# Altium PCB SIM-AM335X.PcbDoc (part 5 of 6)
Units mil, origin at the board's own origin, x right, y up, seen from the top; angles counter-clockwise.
Board outline 4041.51 x 2715.24 mil, 2 copper layers (Top Layer, Bottom Layer); 172 components, 190 nets, 855 pads, 317 vias.
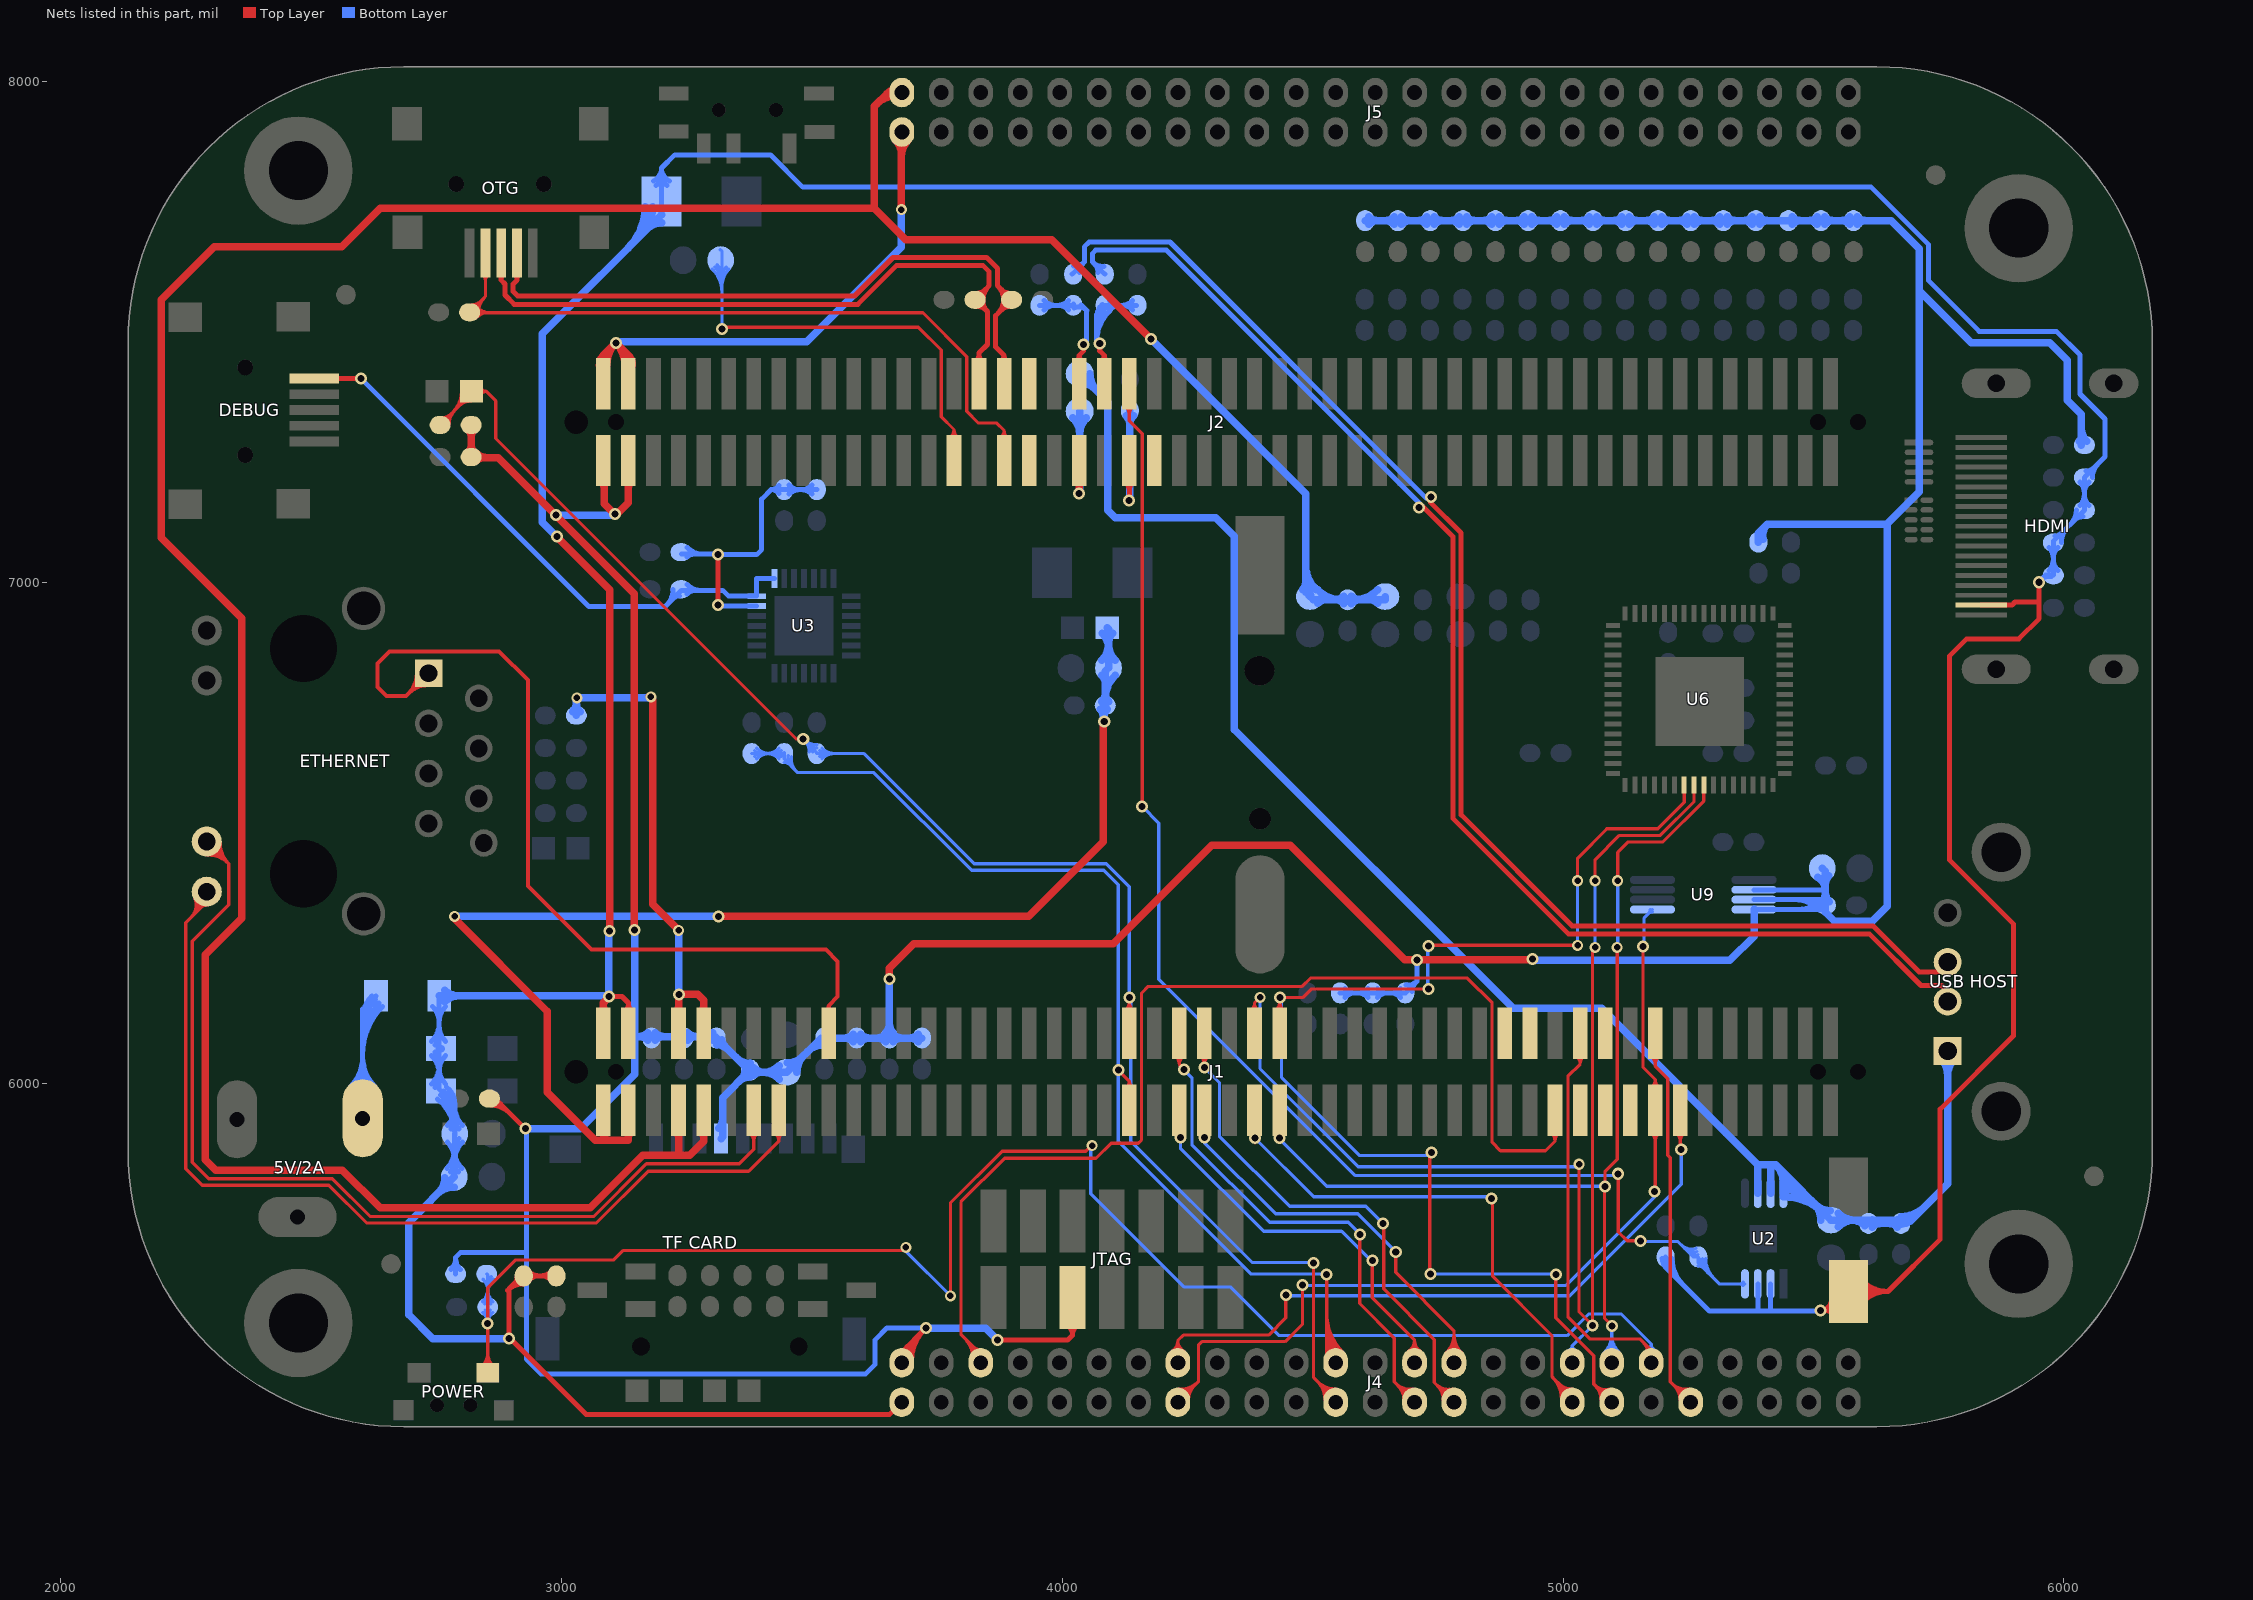
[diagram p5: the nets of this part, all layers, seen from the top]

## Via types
v1: diameter 24, hole 14, Top Layer to Bottom Layer, tented both sides, 206 vias
v2: diameter 22, hole 13, Top Layer to Bottom Layer, tented both sides, 109 vias
v3: diameter 22, hole 14, Top Layer to Bottom Layer, tented both sides, 2 vias

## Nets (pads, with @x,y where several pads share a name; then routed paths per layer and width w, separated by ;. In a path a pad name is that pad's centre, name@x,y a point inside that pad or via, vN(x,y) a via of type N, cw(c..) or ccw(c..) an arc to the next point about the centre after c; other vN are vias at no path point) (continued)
PHY_TX_P: ETHERNET.1 J1.20 | length 1923.7
  Top Layer w8: ETHERNET.1@2711.5,6819.2 cw(c2654.77,6819.2) 2694.88,6779.08 cw(c2735,6738.97) ETHERNET.1@2735,6795.7 ; ETHERNET.1@2719.5,6819.2 cw(c2682.08,6819.2) 2708.54,6792.74 cw(c2735,6766.28) ETHERNET.1@2735,6803.7 ; ETHERNET.1@2735,6819.2 2689.8,6774 2651,6774 2633,6792 2633,6839 2657,6863 2876,6863 2933,6806 2933,6394.49 3059.99,6267.5 3528.5,6267.5 3551.75,6244.25 3551.75,6173.75 3534,6156 ; J1.20@3528.49,6146.17 ccw(c3522.49,6156) 3534,6156 ; J1.20@3534,6100.54 3534,6156 ; J1.20@3539.51,6146.17 cw(c3545.51,6156) 3534,6156
PMIC_INT: J1.81
PMIC_POWR_EN: J1.74
PMIC_RESETOUT: J1.82 | length 5.3
  Top Layer w6.5: J1.82@5084,6100.54 J1.82@5087.75,6096.79
PORZN: J1.83
POWR_EN: J1.76
PWR_BUT: J1.80 J4.40 POWER.1 R41.1 R43.1 | length 4479.4
  Top Layer w6.5: POWER.1@2841.38,5434.12 ccw(c2813.32,5462.18) 2853,5462.18 ccw(c2892.68,5462.18) POWER.1@2864.62,5434.12 ; POWER.1@2845.97,5429.53 ccw(c2829.01,5446.49) 2853,5446.49 ccw(c2876.99,5446.49) POWER.1@2860.03,5429.53 ; POWER.1@2853,5422.5 v1(2853,5521) 2853,5592 2909,5648 3105,5648 3124,5667 3682,5667 v2(3688,5673) ; v2@3691,5670 v2@3694,5673 ; v2(3777,5576) 3777,5762 3880,5865 4047,5865 v2@4062,5880 ; J1.80@5026.55,6055.41 cw(c5012.2,6039) 5034,6039 ; J1.80@5034,6100.54 5034,6039 ; J1.80@5041.45,6055.41 ccw(c5055.8,6039) 5034,6039 ; 5159.18,5484.82 cw(c5134.48,5460.12) J4.40@5167.93,5450.07 ; 5166.87,5477.13 cw(c5146.3,5456.57) J4.40@5174.15,5448.2 ; J4.40@5175.93,5442.74 5175.93,5468.07 5154,5490 5054,5490 5009.68,5534.32 5009.68,6014.68 5034,6039
  Bottom Layer w6.5: R43.1@2842.57,5564.43 ccw(c2817.39,5589.61) 2853,5589.61 ccw(c2888.61,5589.61) R43.1@2863.43,5564.43 ; R43.1@2843.16,5543.01 cw(c2823.46,5521) v1(2853,5521) ; R41.1@2843.57,5609.57 cw(c2820.8,5586.8) 2853,5586.8 ; R43.1@2847.17,5559.83 ccw(c2833.08,5573.92) 2853,5573.92 ccw(c2872.92,5573.92) R43.1@2858.83,5559.83 ; R43.1@2847.5,5547.85 cw(c2836.48,5535.54) 2853,5535.54 cw(c2869.52,5535.54) R43.1@2858.5,5547.85 ; R41.1@2851,5620 2853,5618 R43.1@2853,5554 v1(2853,5521) ; 2853,5581.98 cw(c2892.02,5581.98) R41.1@2864.43,5609.57 ; 2853,5597.67 cw(c2876.33,5597.67) R41.1@2859.83,5614.17 ; R43.1@2862.84,5543.01 ccw(c2882.54,5521) v1(2853,5521) ; v2(3688,5673) 3688,5665 v2(3777,5576) ; v2@4061,5873 4057,5869 4057,5780 4243,5594 4336,5594 4433,5497 5008,5497 5051,5540 5116,5540 5175.93,5480.07 ; J4.40@5167.51,5467.29 ccw(c5162.02,5480.07) 5175.93,5480.07 ; J4.40@5175.93,5442.74 5175.93,5480.07 ; J4.40@5184.35,5467.29 cw(c5189.84,5480.07) 5175.93,5480.07
  other v2: 4060,5876
RTC_PORZN: J1.79
SPI1_CS0: J1.55 J4.38 U6.25 | length 2131.6
  Top Layer w6.5: v1@5083,5795 5083,5531 v1(5098,5516) ; v1(5084,5795) 5084,5824.76 5108.32,5849.08 5108.32,6264.68 5102,6271 5103,6272 v2(5108,6272) ; v2(5109,6405) 5109,6461.5 5130,6482.5 5199.62,6482.5 5281.16,6564.04 U6.25@5281.16,6595.99
  Bottom Layer w6.5: v1@4434,5889 4528,5795 v1(5084,5795) ; J4.38@5082.09,5462.76 ccw(c5045.63,5499.22) 5097.19,5499.22 ccw(c5148.75,5499.22) J4.38@5112.29,5462.76 ; J4.38@5086.69,5458.17 ccw(c5061.32,5483.53) 5097.19,5483.53 ccw(c5133.06,5483.53) J4.38@5107.69,5458.17 ; J4.38@5097.19,5442.74 v1@5097.19,5512.19 ; v2(5108,6272) 5103,6272 5109,6266 v2(5109,6405)
  other v1: 4434,5891
SPI1_D0: J1.54 J4.36 U6.24 | length 2634.2
  Top Layer w6.5: J1.54@4376.85,6145.93 ccw(c4364.55,6161) 4384,6161 ; J1.54@4384,6100.54 4384,6161 ; J1.54@4391.15,6145.93 cw(c4403.45,6161) 4384,6161 ; v2(4395,6172) 4384,6161 ; v2@5032,5842 v2(5032,5839) 5032,5544 v1(5059,5517) 5059,6267 v2(5064,6272) ; v2(5064,6405) 5064,6447 5112.5,6495.5 5194.24,6495.5 5261.47,6562.73 U6.24@5261.47,6595.99
  Bottom Layer w6.5: v2(4395,6172) 4395,6030 4591,5834 5024,5834 v2@5032,5842 ; J4.36@5012.26,5468.1 ccw(c5009.73,5476.45) 5018.45,5476.45 ; J4.36@5018.45,5442.74 5018.45,5476.45 ; J4.36@5024.64,5468.1 cw(c5027.17,5476.45) 5018.45,5476.45 ; v1(5059,5517) 5018.45,5476.45 ; v2(5064,6272) v2(5064,6405)
SPI1_D1: J1.53 J4.35 | length 1263.7
  Top Layer w6.5: J1.53@4376,5902.38 cw(c4356.68,5883.06) 4384,5883.06 cw(c4411.32,5883.06) J1.53@4392,5902.38 ; J1.53@4384,5947 4384,5883 v1@4385,5882 ; v1@4859,5769 4859,5616 4978,5497 4978,5415 ; 4989.11,5403.89 cw(c4954.14,5368.92) J4.35@5003.59,5368.92 ; 4991.6,5401.4 ccw(c5018.45,5428.25) J4.35@5018.45,5390.28 ; J4.35@4997.09,5368.92 ccw(c4931.95,5368.92) 4978.01,5414.99 ; 5000.2,5392.8 cw(c4976.33,5368.92) J4.35@5010.09,5368.92 ; 5002.7,5390.3 ccw(c5018.45,5406.05) J4.35@5018.45,5383.78 ; J4.35@5018.45,5364 5018.45,5374.55 4978,5415
  Bottom Layer w6.5: v1(4385,5891) 4502,5774 v1@4857,5774
  other v1: 4857,5771
SPI1_SCLK: J1.56 J4.37 U6.23 | length 2690.5
  Top Layer w6.5: J1.56@4426,6145.16 ccw(c4404.26,6166.89) v1@4435,6166.89 ; J1.56@4434,6100.54 4435,6101.54 v1(4435,6172) 4481,6172 4498,6189 v1(4731,6189) v1@4730,6188 ; v1@4435,6162.07 ccw(c4458.91,6162.07) J1.56@4442,6145.16 ; v1@4734,5619.77 4734,5857 v1@4737,5857 ; v1@4741,6275 4742,6276 v2(5029,6276) ; v1@4987,5619 v1@4987,5619.98 ; v2(5029,6405) 5029,6450 5087.75,6508.75
  Top Layer w7: v1@4987,5619 4985.8,5617.8 4985.8,5532.2 5061,5457 5061,5400.19 J4.37@5097.19,5364 ; 5063.46,5397.73 ccw(c5085.35,5419.61) J4.37@5092.39,5389.47 ; 5064.64,5396.55 cw(c5037.01,5368.92) J4.37@5076.08,5368.92 ; 5072.36,5388.83 ccw(c5088.72,5405.18) J4.37@5093.98,5382.66 ; 5076.59,5384.6 cw(c5060.91,5368.92) J4.37@5083.08,5368.92 ; 5087.75,6508.75 5188.75,6508.75 5241.78,6561.78 U6.23@5241.78,6595.99
  Bottom Layer w6.5: v1@4438,6170 4438,6012 4593.75,5856.25 v1@4734,5856.25 ; v1@4730,6188 4730,6280 4731,6279 v1(4731,6275) ; v1@4736.63,5619.98 v1@4987.43,5619.98 ; v2@5029,6273 v2(5029,6276) v2(5029,6405)
  other v1: 4986,5619 4735,5620 4737,5862
SYS_RESETN: J1.77 J4.6 | length 2428.2
  Top Layer w6.5: 3803.5,5493.5 cw(c3757.67,5447.66) J4.6@3822.49,5447.66 ; 3814.6,5482.4 cw(c3779.86,5447.66) J4.6@3828.99,5447.66 ; 3821.36,5475.64 ccw(c3837.35,5491.62) J4.6@3837.35,5469.02 ; 3825.7,5471.3 cw(c3802.05,5447.66) J4.6@3835.49,5447.66 ; J4.6@3837.35,5442.74 3837.35,5459.65 3797.75,5499.25 3797.75,5763.75 3885,5851 4067.54,5851 4097.54,5881 4152,5881 4158.32,5887.32 4158.32,6180.32 4172,6194 4479,6194 4495.75,6210.75 4809.04,6210.75 4858.32,6161.47 4858.32,5882.68 4875,5866 4965,5866 4984,5885 ; J1.77@4976.44,5901.97 cw(c4961.19,5885) 4984,5885 ; J1.77@4984,5947 4984,5885 ; J1.77@4991.56,5901.97 ccw(c5006.81,5885) 4984,5885
UART0_RX: J1.43 J4.24 R53.2 R54.1 | length 2750
  Top Layer w6.5: v1(4112,6027) 4134,6005 ; J1.43@4127.64,5992.97 ccw(c4119.45,6005) 4134,6005 ; J1.43@4134,5947 4134,6005 ; J1.43@4140.36,5992.97 cw(c4148.55,6005) 4134,6005 ; 4528,5479.93 ccw(c4578.27,5479.93) J4.24@4542.72,5444.38 ; 4528,5495.62 ccw(c4593.96,5495.62) J4.24@4547.32,5448.97 ; 4528,5511.31 ccw(c4609.66,5511.31) J4.24@4551.92,5453.57 ; 4528,5527 ccw(c4625.35,5527) J4.24@4556.51,5458.17 ; 4528,5542.69 ccw(c4641.04,5542.69) J4.24@4561.11,5462.76 ; v1(4528,5619) 4528,5460.75 J4.24@4546.01,5442.74
  Bottom Layer w6.5: R54.1@3380,6659 R53.2@3445,6659 ; R54.1@3385.83,6653.17 cw(c3399.92,6639.08) 3399.92,6659 cw(c3399.92,6678.92) R54.1@3385.83,6664.83 ; R54.1@3390.43,6648.57 cw(c3415.61,6623.39) 3415.61,6659 cw(c3415.61,6694.61) R54.1@3390.43,6669.43 ; R53.2@3434.57,6648.57 ccw(c3409.39,6623.39) 3409.39,6659 ccw(c3409.39,6694.61) R53.2@3434.57,6669.43 ; R53.2@3439.17,6653.17 ccw(c3425.08,6639.08) 3425.08,6659 ccw(c3425.08,6678.92) R53.2@3439.17,6664.83 ; R53.2@3445,6641.25 cw(c3445,6624.37) 3456.93,6636.31 ; R53.2@3445,6660.76 R53.2@3445,6659 ; R53.2@3453.11,6654.51 ccw(c3476.23,6650.25) 3459.61,6633.63 ; R53.2@3459.51,6653.33 ccw(c3491.01,6647.53) 3468.36,6624.88 ; v1(4528,5619) 4527.25,5619.75 4377.25,5619.75 4112,5885 v1(4112,6027) 4112,6397 4083,6426 3819,6426 3624,6621 3472.24,6621 3445,6648.24 R53.2@3445,6659
UART0_TX: J1.44 J4.23 LED3.2 R19.2 R52.2 | length 3800
  Top Layer w6.5: R19.2@2758,7315 2820.51,7377.51 LED3.2@2820.51,7382.2 2849.8,7382.2 ; R19.2@2761,7329.75 ccw(c2761,7358.12) 2781.06,7338.06 ; R19.2@2769.25,7315 cw(c2796.41,7315) 2777.2,7334.2 ; R19.2@2775.75,7315 cw(c2818.6,7315) 2788.3,7345.3 ; 2783.48,7340.48 ccw(c2741.77,7382.2) LED3.2@2800.76,7382.2 ; 2794.58,7351.58 ccw(c2763.97,7382.2) LED3.2@2807.26,7382.2 ; 2796,7353 cw(c2820.01,7328.99) LED3.2@2820.01,7362.95 ; LED3.2@2805.68,7362.68 ccw(c2786.16,7382.2) LED3.2@2813.76,7382.2 ; LED3.2@2838.8,7374.84 cw(c2849.8,7370.29) 2849.8,7382.2 ; LED3.2@2838.8,7389.55 ccw(c2849.8,7394.1) 2849.8,7382.2 ; v1(3483,6688) 3469,6688 2869,7288 2869,7363 2849.8,7382.2 ; J1.44@4126,6145.16 ccw(c4106.68,6164.48) 4134,6164.48 ccw(c4161.32,6164.48) J1.44@4142,6145.16 ; J1.44@4131,6097.54 J1.44@4134,6100.54 v1(4134,6172) ; v1(4502,5642) 4502,5413.11 4546.01,5369.11 J4.23@4546.01,5364 ; 4509.42,5405.69 cw(c4472.65,5368.92) J4.23@4524.65,5368.92 ; 4509.87,5405.25 ccw(c4546.01,5441.39) J4.23@4546.01,5390.28 ; 4520.52,5394.6 cw(c4494.84,5368.92) J4.23@4531.15,5368.92 ; 4520.96,5394.15 ccw(c4546.01,5419.2) J4.23@4546.01,5383.78
  Bottom Layer w6.5: v1(3483,6688) 3510,6661 R52.2@3510,6659 3604.38,6659 3824.38,6439 4088.38,6439 4134,6393.38 v1(4134,6172) ; v1@3483.5,6687.5 ccw(c3509.46,6713.45) R52.2@3509.84,6676.75 ; v1@3485.53,6685.47 cw(c3462.05,6662) R52.2@3495.25,6662 ; 3494.43,6676.57 ccw(c3509.69,6691.82) R52.2@3509.91,6670.25 ; 3496.62,6674.38 cw(c3484.25,6662) R52.2@3501.75,6662 ; R52.2@3515.83,6653.17 cw(c3529.92,6639.08) 3529.92,6659 cw(c3529.92,6678.92) R52.2@3515.83,6664.83 ; R52.2@3520.43,6648.57 cw(c3545.61,6623.39) 3545.61,6659 cw(c3545.61,6694.61) R52.2@3520.43,6669.43 ; v1@4131,6172 4137,6166 4137,5885 4379,5643 v1@4505,5643
UART1_RXD: J1.47 J4.28 | length 931.5
  Top Layer w6.5: J1.47@4226.69,5901.74 cw(c4213.39,5886) v1@4234,5886 ; J1.47@4234,5947 v1@4234,5886 ; v1@4236,5884 v1@4234,5886 ; J1.47@4241.31,5901.74 ccw(c4254.61,5886) v1@4234,5886 ; v1@4619,5655 4619,5572 4703.49,5487.51 ; J4.28@4691.66,5465.44 ccw(c4676.99,5487.51) 4703.49,5487.51 ; J4.28@4695.26,5460.03 ccw(c4685.05,5475.38) 4703.49,5475.38 ccw(c4721.92,5475.38) J4.28@4711.71,5460.03 ; J4.28@4701.64,5442.74 J4.28@4703.49,5442.74 4703.49,5487.51 ; J4.28@4715.31,5465.44 cw(c4729.99,5487.51) 4703.49,5487.51
  Bottom Layer w6.5: v1@4236,5889 4236,5871 4402,5705 4557.76,5705 4615.76,5647 v1(4619.5,5647)
  other v1: 4236,5892
UART1_TXD: J1.48 J4.27 | length 1183.6
  Top Layer w6.5: J1.48@4226.08,6055.85 cw(c4207.62,6037) 4234,6037 ; J1.48@4234,6100.54 4234,6037 ; J1.48@4241.92,6055.85 ccw(c4260.38,6037) 4234,6037 ; v1(4243,6028) 4234,6037 ; v1(4595,5699) 4594,5698 4594,5561 4663,5492 4663,5404.49 J4.27@4703.49,5364 ; 4665.46,5402.03 ccw(c4695.15,5431.72) J4.27@4700.68,5390.09 ; 4670.51,5396.98 cw(c4642.45,5368.92) J4.27@4682.13,5368.92 ; 4674.77,5392.72 ccw(c4697.34,5415.28) J4.27@4701.53,5383.65 ; 4681.61,5385.88 cw(c4664.65,5368.92) J4.27@4688.63,5368.92
  Bottom Layer w6.5: v1(4243,6028) 4259,6012 4259,5878 4414,5723 4571,5723 v1(4595,5699)
UART2_RXD: J1.49 J4.30 | length 966.7
  Top Layer w6.5: J1.49@4278.9,5900.28 cw(c4274.72,5892) v1(4284,5892) ; v1@4284,5889 v1(4284,5892) ; J1.49@4284,5947 v1(4284,5892) ; J1.49@4289.1,5900.28 ccw(c4293.28,5892) v1(4284,5892) ; v1(4666,5664) 4666,5623 4782.23,5506.77 J4.30@4782.23,5442.74 ; J4.30@4767.13,5462.76 ccw(c4730.67,5499.22) 4782.23,5499.22 ccw(c4833.79,5499.22) J4.30@4797.33,5462.76 ; J4.30@4771.72,5458.17 ccw(c4746.36,5483.53) 4782.23,5483.53 ccw(c4818.09,5483.53) J4.30@4792.73,5458.17
  Bottom Layer w6.5: v1@4284,5882 4426,5740 4590,5740 v1(4666,5664) v1@4672.5,5657.5
UART2_TXD: J1.50 J4.29 | length 1189.6
  Top Layer w6.5: J1.50@4276,6055.93 cw(c4256.68,6036.61) 4284,6036.61 cw(c4311.32,6036.61) J1.50@4292,6055.93 ; v1(4284,6032.25) J1.50@4284,6100.54 ; v1(4641,5721) 4642,5720 4642,5590 4743,5489 4743,5403.23 J4.29@4782.23,5364 ; 4745.46,5400.77 ccw(c4772.65,5427.95) J4.29@4778.81,5390 ; 4749.25,5396.98 cw(c4721.19,5368.92) J4.29@4760.87,5368.92 ; 4754.44,5391.79 ccw(c4775.16,5412.5) J4.29@4779.85,5383.59 ; 4760.35,5385.88 cw(c4743.39,5368.92) J4.29@4767.37,5368.92
  Bottom Layer w6.5: v1(4284,6032.25) 4314,6002.25 4314,5895 4454,5755 4606,5755 4640,5721 v1(4641,5721)
USB0_CE: J2.35
USB0_DRVVBUS: J2.36
USB0_ID: ESD1.1 J2.33 OTG.4 | length 1630.1
  Top Layer w6.5: ESD1.1@2820,7554.75 ccw(c2820,7583.12) 2840.06,7563.06 ; ESD1.1@2825.83,7545.83 ccw(c2842.33,7562.33) 2842.33,7539 ; ESD1.1@2828.25,7540 cw(c2855.41,7540) 2836.2,7559.2 ; ESD1.1@2830.43,7529.57 cw(c2853.2,7506.8) 2853.2,7539 ; ESD1.1@2830.43,7550.43 ccw(c2858.02,7578.02) 2858.02,7539 ; ESD1.1@2834.75,7540 cw(c2877.6,7540) 2847.3,7570.3 ; OTG.4@2843.84,7614.28 cw(c2832.59,7603.03) 2848.5,7603.03 cw(c2864.42,7603.03) OTG.4@2853.17,7614.28 ; OTG.4@2848.5,7658.32 2848.5,7571.5 ESD1.1@2817,7540 2818,7539 3722.08,7539 3809.68,7451.4 3809.68,7342.01 3832.92,7318.77 3869.23,7318.77 3884,7304 ; J2.33@3876.98,7289.49 ccw(c3865.5,7304) 3884,7304 ; J2.33@3884,7244 3884,7304 ; J2.33@3891.02,7289.49 cw(c3902.5,7304) 3884,7304
USB0_N: ESD2.1 J2.34 OTG.2 | length 1498.8
  Top Layer w10: OTG.2@2908.07,7615.52 cw(c2899.81,7607.26) 2911.5,7607.26 cw(c2923.19,7607.26) OTG.2@2914.92,7615.52 ; OTG.2@2911.5,7658.32 2911.5,7604 2904,7596.5 2904,7581.34 2912.83,7572.5 3585.17,7572.5 3662.17,7649.5 3849.08,7649.5 3870.75,7627.83 3870.75,7593.25 ESD2.1@3899,7565 3867.25,7533.25 3867.25,7470.75 3884,7454 ; 3871.69,7537.69 ccw(c3844.37,7565) 3883,7565 ccw(c3844.37,7565) 3871.69,7592.31 ; J2.34@3878.04,7441.64 ccw(c3868.21,7454) 3884,7454 ; 3878.93,7544.93 cw(c3896,7527.86) ESD2.1@3896,7552 ; 3878.93,7585.07 ccw(c3896,7602.14) ESD2.1@3896,7578 ; J2.34@3884,7397.54 3884,7454 ; J2.34@3889.96,7441.64 cw(c3899.79,7454) 3884,7454
USB0_P: ESD3.1 J2.32 OTG.3 | length 1500.7
  Top Layer w10: OTG.3@2876.58,7615.52 cw(c2868.31,7607.26) 2880,7607.26 cw(c2891.69,7607.26) OTG.3@2883.42,7615.52 ; OTG.3@2880,7658.32 2880,7604 2887.5,7596.5 2887.5,7574.5 2906,7556 3592,7556 3669,7633 3842.25,7633 3854.25,7621 3854.25,7593.25 ESD3.1@3826,7565 3827.42,7565 3850.75,7541.67 3850.75,7475.75 3834,7459 J2.32@3834,7397.54 ; J2.32@3827.24,7440.92 ccw(c3810.9,7457.25) 3834,7457.25 ccw(c3857.1,7457.25) J2.32@3840.76,7440.92 ; ESD3.1@3829,7552 cw(c3829,7524.44) 3848.49,7543.93 ; ESD3.1@3829,7578 ccw(c3829,7602.14) 3846.07,7585.07 ; ESD3.1@3841.96,7564.02 ccw(c3869.45,7561.95) 3849.96,7542.46 ; ESD3.1@3842,7565 cw(c3880.63,7565) 3853.31,7592.31
USB0_VBUS: FB2.1 J2.29 | length 1065.5
  Top Layer w6.5: v1(3321,7507) 3324,7510 3713,7510 3758.32,7464.68 3758.32,7331.68 3784,7306 ; J2.29@3776.44,7289.03 ccw(c3761.19,7306) 3784,7306 ; J2.29@3784,7244 3784,7306 ; J2.29@3791.56,7289.03 cw(c3806.81,7306) 3784,7306
  Bottom Layer w6.5: FB2.1@3301.56,7626.06 cw(c3254.63,7579.13) 3321,7579.13 ; FB2.1@3306.16,7630.66 cw(c3270.32,7594.82) 3321,7594.82 ; FB2.1@3310.75,7635.25 cw(c3286.01,7610.51) 3321,7610.51 ; FB2.1@3317.5,7665 3321,7661.5 v1(3321,7507) ; 3321,7593.61 cw(c3366.89,7593.61) FB2.1@3334.44,7626.06 ; 3321,7609.3 cw(c3351.2,7609.3) FB2.1@3329.84,7630.66
USB1_CE: J2.45
USB1_DRVVBUS: J2.44 R59.1 U2.4 | length 2961.7
  Top Layer w6.5: J2.44@4126,7352.93 cw(c4106.68,7333.61) 4134,7333.61 cw(c4161.32,7333.61) J2.44@4142,7352.93 ; J2.44@4134,7397.54 4134,7323.54 4159.68,7297.85 v1(4159.68,6553.32) v1@4160,6553 ; v1(5110,5820) 5110,5703.77 5127.77,5686 v1(5155,5686) v1@5164,5686
  Bottom Layer w6.5: v1(4159.68,6553.32) 4193,6520 4193,6208.24 4584.49,5816.75 5106.75,5816.75 v1(5110,5820) ; v1@5164,5684.75 5229.25,5684.75 5260,5654 R59.1@5270,5654 5270,5642 5312,5600 U2.4@5363.23,5600 ; 5235.75,5678.25 ccw(c5256.53,5699.03) R59.1@5265.5,5671.05 ; 5243.28,5670.72 ccw(c5260.18,5687.62) R59.1@5267.48,5664.86 ; 5250.82,5663.18 ccw(c5263.84,5676.21) R59.1@5269.47,5658.67 ; R59.1@5270,5636.25 cw(c5270,5622.37) 5279.82,5632.18 ; R59.1@5271.75,5651 ccw(c5297.7,5651) 5279.35,5632.65 ; R59.1@5278.25,5651 ccw(c5319.9,5651) 5290.45,5621.55 ; R59.1@5284.75,5651 ccw(c5342.09,5651) 5301.54,5610.46 ; U2.4@5359.96,5596.73 ccw(c5352.06,5588.84) 5352.06,5600 ccw(c5352.06,5611.16) U2.4@5359.96,5603.27
USB1_ID: J2.43 R57.2 | length 348.8
  Top Layer w6.5: v1@4134,7164 v1@4138,7160
  Top Layer w10: J2.43@4127.24,7200.62 cw(c4110.9,7184.29) 4134,7184.29 cw(c4157.1,7184.29) J2.43@4140.76,7200.62 ; v1@4134,7164 J2.43@4134,7244
  Bottom Layer w6.5: v1@4135,7168 4138,7168 v1@4138,7160
  Bottom Layer w15: R57.2@4127.58,7333.58 cw(c4109.65,7315.65) 4135,7315.65 cw(c4160.35,7315.65) R57.2@4142.42,7333.58 ; v1@4135,7168 R57.2@4135,7344
  other v1: 4133,7164
USB1_N: ESD4.1 J2.42 R49.2 | length 502.4
  Top Layer w10: v1(4075,7478) 4075,7463 4084,7454 ; J2.42@4078.04,7441.64 ccw(c4068.21,7454) 4084,7454 ; J2.42@4084,7397.54 4084,7454 ; J2.42@4089.96,7441.64 cw(c4099.79,7454) 4084,7454
  Bottom Layer w10: v1@4069,7482.12 cw(c4152.3,7482.12) R49.2@4094.09,7541.7 ; 4069,7505.87 cw(c4129.09,7505.87) R49.2@4087.1,7548.85 ; 4069,7529.62 cw(c4105.89,7529.62) R49.2@4080.11,7556.01 ; v1(4075,7478) 4069,7484 4069,7536 R49.2@4081,7548 ; R49.2@4080,7549 R49.2@4085,7554 ESD4.1@4148,7554 ; R49.2@4094.19,7544.81 cw(c4116.38,7522.62) 4116.38,7554 cw(c4116.38,7585.38) R49.2@4094.19,7563.19 ; ESD4.1@4140.81,7544.81 ccw(c4118.62,7522.62) 4118.62,7554 ccw(c4118.62,7585.38) ESD4.1@4140.81,7563.19
USB1_P: ESD5.1 J2.40 R48.2 | length 393.3
  Top Layer w10: J2.40@4028.04,7441.64 ccw(c4018.21,7454) 4034,7454 ; J2.40@4034,7397.54 4034,7454 ; J2.40@4039.96,7441.64 cw(c4049.79,7454) 4034,7454 ; v1(4043,7476) 4043,7463 4034,7454
  Bottom Layer w10: ESD5.1@3955,7554 4020,7554 4021,7555 R48.2@4023,7557 ; ESD5.1@3964.19,7544.81 cw(c3986.38,7522.62) 3986.38,7554 cw(c3986.38,7585.38) ESD5.1@3964.19,7563.19 ; R48.2@4012.81,7544.81 ccw(c3990.62,7522.62) 3990.62,7554 ccw(c3990.62,7585.38) R48.2@4012.81,7563.19 ; R48.2@4022,7554 R48.2@4023,7554 ; R48.2@4023.31,7548.3 cw(c4033.12,7528.01) 4049.05,7543.95 ; R48.2@4038,7555 4049,7544 4049,7482 v1(4043,7476)
USB1_VBUS: FB1.2 J2.39 | length 329.8
  Top Layer w15: J2.39@4029,7202.39 cw(c4016.94,7190.32) 4034,7190.32 cw(c4051.06,7190.32) J2.39@4039,7202.39 ; v1(4034,7178) J2.39@4034,7244
  Bottom Layer w15: FB1.2@4021.56,7329.06 cw(c3989.13,7296.63) 4035,7296.63 cw(c4080.87,7296.63) FB1.2@4048.44,7329.06 ; v1(4034,7178) 4035,7179 FB1.2@4035,7342.5
USB2_N: "USB HOST.2" R49.1 | length 2771.1
  Top Layer w6.5: v1@4713,7151 v1@4721.33,7151
  Top Layer w10: v1@4721.33,7151 4780,7092.33 4780,6529.67 5011.17,6298.5 5612.17,6298.5 5714.67,6196 5756,6196 5768,6184 5768,6163.83
  Bottom Layer w6.5: v1@4713,7151 v1@4713,7159.33
  Bottom Layer w10: 4062.25,7638.75 ccw(c4079.52,7656.02) R49.1@4083.1,7631.86 ; 4064.93,7636.07 cw(c4047.86,7619) R49.1@4072,7619 ; R49.1@4085,7616 4060.75,7640.25 4060.75,7657.75 4067,7664 4208.33,7664 v1@4713,7159.33
  other v1: 4712,7150
USB2_P: "USB HOST.3" R48.1 | length 2776.5
  Top Layer w6.5: 5619,6315 5620.75,6313.25
  Top Layer w10: v1@4735,7160.67 4796.5,7099.17 4796.5,6536.5 5018,6315 5619,6315 ; 5620.75,6313.25 5711,6223 5748,6223 5764,6239 ; 5768,6242.57 5766.57,6242.57 5769,6245
  Bottom Layer w6.5: v1@4726.67,7169 v1@4735,7169
  Bottom Layer w10: R48.1@4020,7616 4044.25,7640.25 ; R48.1@4022.69,7631.98 ccw(c4024.19,7660.3) 4044.25,7640.25 ; R48.1@4035,7619 cw(c4063.97,7619) 4043.49,7639.49 ; v1@4726.67,7169 4215.17,7680.5 4053.92,7680.5 4044.25,7670.83 4044.25,7640.25
  other v1: 4736,7171
USB_3V3: C24.1 C27.1 R51.1 U3.6 | length 735.1
  Top Layer w10: v1@3313,6955 v1(3313,6956) v1@3313,7054
  Bottom Layer w10: C27.1@3240,7057 v1@3304,7057 ; C27.1@3251.19,7051.81 cw(c3263.73,7039.27) 3263.73,7057 ; C27.1@3251.19,7070.19 ccw(c3283.04,7102.04) 3283.04,7057 ; v1(3313,6956) 3315.58,6953.42 U3.6@3390,6953.42 ; v1(3313,7056) 3390,7056 3400,7066 3400,7167 3419,7186 ; R51.1@3434.6,7178.2 ccw(c3419,7166.5) 3419,7186 ; R51.1@3434.6,7193.8 cw(c3419,7205.5) 3419,7186 ; R51.1@3454.19,7176.81 cw(c3476.38,7154.62) 3476.38,7186 cw(c3476.38,7217.38) R51.1@3454.19,7195.19 ; C24.1@3500.81,7176.81 ccw(c3478.62,7154.62) 3478.62,7186 ccw(c3478.62,7217.38) C24.1@3500.81,7195.19 ; C24.1@3510,7186 R51.1@3445,7186 3419,7186
USB_5V: "USB HOST.1" C22.2 C23.1 C25.1 FB1.1 U2.6 U2.7 U2.8 | length 4109.8
  Bottom Layer w15: FB1.1@4035,7417.5 4091,7361.5 4091,7145 4106,7130 4307,7130 4344,7093 4344,6707 4901,6150 5077,6150 5388.82,5838.18 ; FB1.1@4036.5,7398.5 cw(c4036.5,7356.25) 4066.37,7386.13 ; FB1.1@4055.5,7417.5 ccw(c4104.99,7417.5) 4070,7382.5 ; U2.6@5388.82,5781.1 5388.82,5838.18 ; U2.7@5414.41,5781.1 5414.41,5833.77 ; 5425.4,5837.1 cw(c5391.06,5802.76) U2.8@5439.63,5802.76 ; U2.8@5440,5774.07 cw(c5440,5657.16) C25.1@5522.67,5739.83 ; U2.8@5440,5781.1 5440,5818 ; U2.8@5440,5789.07 cw(c5440,5708.38) 5497.06,5765.44 ; U2.8@5440,5804.07 cw(c5440,5759.59) 5471.45,5791.05 ; 5451.01,5811.49 cw(c5442.27,5802.76) 5454.63,5802.76 ; 5500,5762.5 cw(c5465.01,5727.5) C25.1@5514.5,5727.5 ; 5503.63,5758.87 ccw(c5533.5,5788.75) C25.1@5533.5,5746.5 ; C25.1@5549.94,5714.06 cw(c5582.37,5681.63) 5582.37,5727.5 cw(c5582.37,5773.37) C25.1@5549.94,5740.94 ; 5576.2,5727.5 cw(c5576.2,5690.2) C23.1@5602.58,5716.58 ; C23.1@5610,5721 C22.2@5659,5721 ; C23.1@5617.42,5713.58 cw(c5635.35,5695.65) 5635.35,5721 cw(c5635.35,5746.35) C23.1@5617.42,5728.42 ; C23.1@5617.42,5716.58 cw(c5643.8,5690.2) 5643.8,5727.5 ; 5641.2,5727.5 cw(c5641.2,5690.2) C22.2@5667.58,5716.58 ; C22.2@5667.58,5713.58 ccw(c5649.65,5695.65) 5649.65,5721 ccw(c5649.65,5746.35) C22.2@5667.58,5728.42 ; C22.2@5675,5719.5 ccw(c5675,5749.68) 5696.34,5728.34 ; C22.2@5675,5721 C22.2@5659,5721 ; C22.2@5675,5734.5 ccw(c5675,5800.89) 5721.95,5753.95 ; 5753.54,6050.95 cw(c5718.62,6016.03) 5768,6016.03 cw(c5817.38,6016.03) 5782.46,6050.95 ; 5768,6065.41 5768,5800 5695.5,5727.5 5652.5,5727.5 ; 5388.82,5838.18 5424.32,5838.18 C25.1@5535,5727.5 5652.5,5727.5 ; 5652.5,5727.5 cw(c5652.5,5712.92) 5665.58,5719.36 ccw(c5652.5,5712.92) 5652.5,5727.5 ; 5652.5,5727.5 C22.2@5659,5721
VBUS: C28.1 DEBUG.1 U3.7 U3.8 | length 1277.4
  Top Layer w10: DEBUG.1@2506.69,7407.99 v1(2599.71,7408) ; DEBUG.1@2549.48,7404.57 cw(c2557.75,7396.3) 2557.75,7407.99 cw(c2557.75,7419.68) DEBUG.1@2549.48,7411.42
  Bottom Layer w10: v1(2599.71,7408) 3055.36,6952.35 3207.43,6952.35 3240.08,6985 3322.17,6985 3334.06,6973.11 U3.7@3390,6973.11 3389.54,6973.57 3389.54,7008.54 U3.8@3425.43,7008.54 ; 3210.47,6955.39 ccw(c3180.19,6985.67) C28.1@3223,6986.69 ; 3224.19,6969.11 cw(c3236,6957.3) C28.1@3236,6974 ; C28.1@3251.19,6977.81 cw(c3268.56,6960.44) 3268.56,6985 ; C28.1@3251.19,6996.19 ccw(c3278.21,7023.21) 3278.21,6985
VCC3V3_BAT: C3.1 C4.2 J1.1 J1.3 R44.1 | length 2872.6
  Top Layer w15: v2(2787,6334) 2787,6329 2972,6144 2972,5983 3068,5887 3087,5887 ; J1.1@3079.11,5905.28 cw(c3061.43,5886.81) 3087,5886.81 ; J1.1@3084,5947 3087,5944 3087,5887 ; J1.3@3129,5905.39 cw(c3116.94,5893.32) 3134,5893.32 cw(c3151.06,5893.32) J1.3@3139,5905.39 ; J1.3@3134,5947 3134,5887 3087,5887 ; v1(3314,6334) 3933,6334 4082.32,6483.32 4082.32,6721.32 v1(4084,6723)
  Bottom Layer w15: v2(2787,6334) v1(3314,6334) ; C3.1@4075.58,6747.58 cw(c4059.3,6731.3) v1@4082.32,6731.3 ; C3.1@4078.58,6762.42 ccw(c4060.65,6780.35) 4086,6780.35 ccw(c4111.35,6780.35) C3.1@4093.42,6762.42 ; C4.2@4079.06,6815.06 cw(c4062.32,6798.32) 4086,6798.32 ; C4.2@4079.06,6844.94 ccw(c4046.63,6877.37) 4092.5,6877.37 ccw(c4138.37,6877.37) C4.2@4105.94,6844.94 ; R44.1@4079.89,6899.39 cw(c4049.46,6868.96) 4092.5,6868.96 ; v1@4082.32,6728 cw(c4110,6728) C3.1@4090.42,6747.58 ; v1(4084,6723) 4082.32,6721.32 4082.32,6751.32 C3.1@4086,6755 4086,6823.5 C4.2@4092.5,6830 4092.5,6907.5 R44.1@4090,6910 ; C3.1@4086,6766.94 cw(c4154.06,6766.94) C4.2@4105.94,6815.06 ; 4092.5,6878.62 cw(c4121.88,6878.62) R44.1@4101.11,6899.39
VDD_1V8: C54.2 C56.1 FB5.1 J1.7 J1.9 J5.2 | length 6748.9
  Top Layer w15: J1.7@3229,5905.39 cw(c3216.94,5893.32) 3234,5893.32 cw(c3251.06,5893.32) J1.7@3239,5905.39 ; J1.7@3234,5947 3234,5858.93 3232.32,5857.25 ; J1.9@3279,5905.39 cw(c3266.94,5893.32) 3284,5893.32 cw(c3301.06,5893.32) J1.9@3289,5905.39 ; J1.9@3284,5947 3284,5885 3256.25,5857.25 3232.32,5857.25 ; 3629.29,7955.66 cw(c3670.06,7914.89) J5.2@3679.65,7971.74 ; 3649.85,7976.22 cw(c3675.99,7950.07) J5.2@3682.14,7986.53 ; J5.2@3680,7978.74 3652.37,7978.74 3625,7951.37 3625,7747.46 ; v1(4177,7487) 3979,7685 3687.46,7685 3625,7747.46 ; 3232.32,5857.25 3162.78,5857.25 3057.47,5751.94 2638.06,5751.94 2562.75,5827.25 2309.75,5827.25 2289,5848 2289,6257 2362,6330 2362,6929 2201.54,7089.46 2201.54,7565.4 2307.14,7671 2562,7671 2638.46,7747.46 3625,7747.46
  Bottom Layer w15: v1(4177,7487) 4486,7178 4486,6981.5 C54.2@4495,6972.5 ; C54.2@4480.06,6985.94 ccw(c4465.74,7000.26) 4486,7000.26 ccw(c4521.26,7000.26) C54.2@4496.33,6975.33 ; 4486,7036.48 ccw(c4557.48,7036.48) C54.2@4506.94,6985.94 ; C54.2@4501.5,6966 C56.1@4570,6966 4645,6966 FB5.1@4645,6972.5 ; C54.2@4509.94,6959.06 cw(c4526.68,6942.32) 4526.68,6966 ; C54.2@4509.94,6985.94 ccw(c4558.06,7034.06) C56.1@4558.06,6966 ; C56.1@4562.58,6958.58 ccw(c4544.65,6940.65) 4544.65,6966 ccw(c4544.65,6991.35) C56.1@4562.58,6973.42 ; C56.1@4577.42,6958.58 cw(c4595.35,6940.65) 4595.35,6966 cw(c4595.35,6991.35) C56.1@4577.42,6973.42 ; C56.1@4581.94,6966 ccw(c4581.94,7034.06) FB5.1@4630.06,6985.94 ; 4613.32,6966 cw(c4613.32,6942.32) FB5.1@4630.06,6959.06
VDD_3V3A: J2.2 J2.4 J5.1 | length 1316.2
  Top Layer w15: J2.2@3076.07,7433.98 cw(c3103.75,7434.59) 3084.17,7454.17 ; J2.2@3079,7439.16 ccw(c3066.94,7451.22) 3084,7451.22 ccw(c3101.06,7451.22) J2.2@3089,7439.16 ; J2.2@3084,7397.54 3084,7454 v1(3109,7479) ; J2.2@3091.07,7434.31 cw(c3152.33,7435.67) v1(3109,7479) ; v1@3107.91,7480.09 cw(c3061.97,7434.16) J2.4@3126.93,7434.16 ; J2.4@3129,7439.16 ccw(c3116.94,7451.22) 3134,7451.22 ccw(c3151.06,7451.22) J2.4@3139,7439.16 ; 3133.51,7454.49 cw(c3113.18,7434.16) J2.4@3141.93,7434.16 ; J2.4@3134,7397.54 3134,7454 v1(3109,7479) ; J5.1@3667.9,7882.98 cw(c3641.12,7856.19) 3679,7856.19 ; v2(3679,7745) 3679,7899 J5.1@3680,7900 ; 3679,7851.37 cw(c3723.71,7851.37) J5.1@3692.1,7882.98
  Bottom Layer w15: v1@3119,7481 3490,7481 3679,7670 v2(3679,7745)
VDD_3V3B: "TF CARD.4" C30.2 C31.1 C32.1 C82.2 C83.1 J2.1 J2.3 J4.2 JTAG.5 R1.1 R2.1 R3.1 R4.1 R5.1 R6.1 R7.1 R8.1 R9.1 R10.1 R11.1 R12.1 R13.1 R14.1 R15.1 R16.1 R19.1 R21.1 R41.2 R42.1 R55.1 R56.1 R67.1 R68.1 R69.1 R70.1 R71.1 R72.1 R73.1 R92.2 R95.1 U9.6 U9.7 U9.8 | length 14321.7
  Top Layer w10: R42.1@2856.49,5970 2868,5970 v1(2928,5910) ; R42.1@2859.49,5957 cw(c2859.49,5905.07) 2896.21,5941.79 ; R42.1@2859.49,5967 cw(c2859.49,5939.21) 2879.14,5958.86 ; J2.1@3084,7244 3084,7203 J2.1@3086,7201 ; v1(3107,7137) v1@3111,7137 ; J4.2@3679.47,5447.66 cw(c3717.64,5447.66) 3690.65,5474.65 ; J4.2@3679.87,5442.74 3679.87,5463.87 v1(3728,5512) ; J4.2@3689.47,5447.66 cw(c3751.79,5447.66) 3707.72,5491.72 ; J4.2@3699.47,5447.66 cw(c3785.93,5447.66) v1@3724.79,5508.79 ; v1(3871,5488) 4011,5488 4020.48,5497.48 ; JTAG.5@4009.19,5518.38 cw(c3995.49,5497.48) 4020.48,5497.48 ; JTAG.5@4020.48,5573 4020.48,5497.48 ; JTAG.5@4031.77,5518.38 ccw(c4045.47,5497.48) 4020.48,5497.48
  Top Layer w15: R21.1@2812.58,7258.42 ccw(c2794.65,7276.35) 2820,7276.35 ccw(c2845.35,7276.35) R21.1@2827.42,7258.42 ; R19.1@2812.58,7307.58 cw(c2794.65,7289.65) 2820,7289.65 cw(c2845.35,7289.65) R19.1@2827.42,7307.58 ; R19.1@2820,7315 R21.1@2820,7251 2820,7249.71 2874.29,7249.71 v1(2989,7135) 3146,6978 v1(3146,6307) ; R21.1@2830.42,7243.58 cw(c2845.23,7228.77) 2845.23,7249.71 ; R21.1@2830.42,7258.42 ccw(c2851.47,7279.47) 2851.47,7249.71 ; J2.1@3079,7202.39 cw(c3062.11,7185.5) 3086,7185.5 ; J2.1@3086,7201 3086,7158 v1(3107,7137) ; v1@3111,7137 3134,7160 J2.3@3134,7244 ; J2.3@3129,7202.39 cw(c3116.94,7190.32) 3134,7190.32 cw(c3151.06,7190.32) J2.3@3139,7202.39 ; v1(3655,6209) 3655,6230.23 3703.77,6279 4102,6279 4299,6476 4455,6476 4684,6247 v1(4708,6247) v1@4939,6247
  Bottom Layer w10: R41.2@2779.81,5629.19 ccw(c2757.62,5651.38) 2789,5651.38 ccw(c2820.38,5651.38) R41.2@2798.19,5629.19 ; R41.2@2789,5620 2789,5653 2799,5663 2930,5663 ; v1(2928,5910) 2930,5908 2930,5663 ; C31.1@3377,6015 C31.1@3377,6024 ; v1@3733,5512 v1(3728,5512) 3650,5512 3626.53,5488.53 3626.53,5439.53 3607,5420 2959.74,5420 2930,5449.74 2930,5663 ; C32.1@4555,6181 R72.1@4620,6181 R73.1@4685,6181 4708,6204 ; C32.1@4564.19,6171.81 cw(c4586.38,6149.62) 4586.38,6181 cw(c4586.38,6212.38) C32.1@4564.19,6190.19 ; R72.1@4610.81,6171.81 ccw(c4588.62,6149.62) 4588.62,6181 ccw(c4588.62,6212.38) R72.1@4610.81,6190.19 ; R72.1@4629.19,6171.81 cw(c4651.38,6149.62) 4651.38,6181 cw(c4651.38,6212.38) R72.1@4629.19,6190.19 ; R73.1@4675.81,6171.81 ccw(c4653.62,6149.62) 4653.62,6181 ccw(c4653.62,6212.38) R73.1@4675.81,6190.19 ; R73.1@4686.78,6196.88 ccw(c4690.23,6221.77) 4708,6204 ; R73.1@4698,6184 cw(c4722.14,6184) 4705.07,6201.07 ; v1(4708,6247) 4708,6204 ; U9.8@5381.38,6347.67 5515.67,6347.67 C83.1@5524,6356 5512.65,6367.35 U9.7@5381.38,6367.35 ; U9.6@5381.38,6387.04 5522.96,6387.04 5524,6386 ; 5462.2,6367.35 cw(c5462.2,6297.2) C83.1@5511.81,6346.81 ; 5469.5,6347.67 ccw(c5469.5,6407.5) C83.1@5511.81,6365.19 ; 5486.35,6367.35 cw(c5486.35,6321.35) C83.1@5518.88,6353.88 ; 5493.65,6347.67 ccw(c5493.65,6383.35) C83.1@5518.88,6358.12
  Bottom Layer w15: v1(2928,5910) 2928.26,5910.26 3038.26,5910.26 3147,6019 3147,6094 ; v1(2989,7135) 3105,7135 v1(3107,7137) ; v1@3147,6300 3147,6094 ; R55.1@3172.58,6086.58 ccw(c3154.65,6068.65) 3154.65,6094 ccw(c3154.65,6119.35) R55.1@3172.58,6101.42 ; R55.1@3187.42,6086.58 cw(c3205.35,6068.65) 3205.35,6094 cw(c3205.35,6119.35) R55.1@3187.42,6101.42 ; R56.1@3237.58,6086.58 ccw(c3219.65,6068.65) 3219.65,6094 ccw(c3219.65,6119.35) R56.1@3237.58,6101.42 ; R56.1@3252.42,6086.58 cw(c3270.35,6068.65) 3270.35,6094 cw(c3270.35,6119.35) R56.1@3252.42,6101.42 ; R67.1@3302.58,6086.58 ccw(c3284.65,6068.65) 3284.65,6094 ccw(c3284.65,6119.35) R67.1@3302.58,6101.42 ; R67.1@3310,6077.5 cw(c3310,6044.91) 3333.05,6067.95 ; 3314.5,5910.54 ccw(c3296.39,5928.65) 3322,5928.65 ; 3318.94,5890.35 3322,5893.42 3322,5972 C31.1@3375.5,6025.5 ; R67.1@3320.5,6088 ccw(c3338.61,6088) 3325.8,6075.2 ; 3348.83,6052.17 ccw(c3377,6080.33) C31.1@3377,6040.5 ; 3353.95,6003.95 cw(c3377,5980.91) C31.1@3377,6013.5 ; 3361.2,6011.2 ccw(c3348.39,6024) C31.1@3366.5,6024 ; C31.1@3377,6024 3378.5,6022.5 C30.2@3450,6022.5 3518.5,6091 R68.1@3525,6091 R69.1@3590,6091 R70.1@3655,6091 ; C31.1@3377,6027 C31.1@3375.5,6025.5 ; C31.1@3384.42,6016.58 cw(c3398.73,6002.27) 3398.73,6022.5 ; C31.1@3384.42,6031.42 ccw(c3405.97,6052.97) 3405.97,6022.5 ; C30.2@3435.06,6009.06 ccw(c3402.63,5976.63) 3402.63,6022.5 ccw(c3402.63,6068.37) C30.2@3435.06,6035.94 ; C30.2@3451.5,6041.5 ccw(c3451.5,6083.75) 3481.37,6053.87 ; C30.2@3470.5,6022.5 cw(c3519.99,6022.5) 3485,6057.5 ; 3490.86,6063.36 cw(c3525,6029.22) R68.1@3525,6077.5 ; R68.1@3532.42,6083.58 cw(c3550.35,6065.65) 3550.35,6091 cw(c3550.35,6116.35) R68.1@3532.42,6098.42 ; R69.1@3582.58,6083.58 ccw(c3564.65,6065.65) 3564.65,6091 ccw(c3564.65,6116.35) R69.1@3582.58,6098.42 ; R69.1@3597.42,6083.58 cw(c3615.35,6065.65) 3615.35,6091 cw(c3615.35,6116.35) R69.1@3597.42,6098.42 ; R70.1@3647.58,6083.58 ccw(c3629.65,6065.65) 3629.65,6091 ccw(c3629.65,6116.35) R70.1@3647.58,6098.42 ; R70.1@3647.58,6101.42 ccw(c3629.65,6119.35) 3655,6119.35 ccw(c3680.35,6119.35) R70.1@3662.42,6101.42 ; v1(3655,6209) R70.1@3655,6091 ; R70.1@3662.42,6083.58 cw(c3680.35,6065.65) 3680.35,6091 cw(c3680.35,6116.35) R70.1@3662.42,6098.42 ; R71.1@3712.58,6083.58 ccw(c3694.65,6065.65) 3694.65,6091 ccw(c3694.65,6116.35) R71.1@3712.58,6098.42 ; R71.1@3720,6091 R70.1@3655,6091 ; v1@3733,5512 3847,5512 v1(3871,5488) ; R16.1@4605,7723 R15.1@4670,7723 R14.1@4735,7723 R13.1@4800,7723 R12.1@4865,7723 R11.1@4930,7723 R10.1@4995,7723 R9.1@5060,7723 R8.1@5125,7723 R7.1@5190,7723 R6.1@5255,7723 R5.1@5320,7723 R4.1@5385,7723 R3.1@5450,7723 R2.1@5515,7723 R1.1@5580,7723 5655,7723 5711,7667 5711,7583.13 ; R16.1@4612.42,7715.58 cw(c4630.35,7697.65) 4630.35,7723 cw(c4630.35,7748.35) R16.1@4612.42,7730.42 ; R15.1@4662.58,7715.58 ccw(c4644.65,7697.65) 4644.65,7723 ccw(c4644.65,7748.35) R15.1@4662.58,7730.42 ; R15.1@4677.42,7715.58 cw(c4695.35,7697.65) 4695.35,7723 cw(c4695.35,7748.35) R15.1@4677.42,7730.42 ; R14.1@4727.58,7715.58 ccw(c4709.65,7697.65) 4709.65,7723 ccw(c4709.65,7748.35) R14.1@4727.58,7730.42 ; R14.1@4742.42,7715.58 cw(c4760.35,7697.65) 4760.35,7723 cw(c4760.35,7748.35) R14.1@4742.42,7730.42 ; R13.1@4792.58,7715.58 ccw(c4774.65,7697.65) 4774.65,7723 ccw(c4774.65,7748.35) R13.1@4792.58,7730.42 ; R13.1@4807.42,7715.58 cw(c4825.35,7697.65) 4825.35,7723 cw(c4825.35,7748.35) R13.1@4807.42,7730.42 ; R12.1@4857.58,7715.58 ccw(c4839.65,7697.65) 4839.65,7723 ccw(c4839.65,7748.35) R12.1@4857.58,7730.42 ; R12.1@4872.42,7715.58 cw(c4890.35,7697.65) 4890.35,7723 cw(c4890.35,7748.35) R12.1@4872.42,7730.42 ; R11.1@4922.58,7715.58 ccw(c4904.65,7697.65) 4904.65,7723 ccw(c4904.65,7748.35) R11.1@4922.58,7730.42 ; R11.1@4937.42,7715.58 cw(c4955.35,7697.65) 4955.35,7723 cw(c4955.35,7748.35) R11.1@4937.42,7730.42 ; v1@4939,6246 5333,6246 5381.38,6294.38 U9.8@5381.38,6347.67 ; R10.1@4987.58,7715.58 ccw(c4969.65,7697.65) 4969.65,7723 ccw(c4969.65,7748.35) R10.1@4987.58,7730.42 ; R10.1@5002.42,7715.58 cw(c5020.35,7697.65) 5020.35,7723 cw(c5020.35,7748.35) R10.1@5002.42,7730.42 ; R9.1@5052.58,7715.58 ccw(c5034.65,7697.65) 5034.65,7723 ccw(c5034.65,7748.35) R9.1@5052.58,7730.42 ; R9.1@5067.42,7715.58 cw(c5085.35,7697.65) 5085.35,7723 cw(c5085.35,7748.35) R9.1@5067.42,7730.42 ; R8.1@5117.58,7715.58 ccw(c5099.65,7697.65) 5099.65,7723 ccw(c5099.65,7748.35) R8.1@5117.58,7730.42 ; R8.1@5132.42,7715.58 cw(c5150.35,7697.65) 5150.35,7723 cw(c5150.35,7748.35) R8.1@5132.42,7730.42 ; R7.1@5182.58,7715.58 ccw(c5164.65,7697.65) 5164.65,7723 ccw(c5164.65,7748.35) R7.1@5182.58,7730.42 ; R7.1@5197.42,7715.58 cw(c5215.35,7697.65) 5215.35,7723 cw(c5215.35,7748.35) R7.1@5197.42,7730.42 ; R6.1@5247.58,7715.58 ccw(c5229.65,7697.65) 5229.65,7723 ccw(c5229.65,7748.35) R6.1@5247.58,7730.42 ; R6.1@5262.42,7715.58 cw(c5280.35,7697.65) 5280.35,7723 cw(c5280.35,7748.35) R6.1@5262.42,7730.42 ; R5.1@5312.58,7715.58 ccw(c5294.65,7697.65) 5294.65,7723 ccw(c5294.65,7748.35) R5.1@5312.58,7730.42 ; R5.1@5327.42,7715.58 cw(c5345.35,7697.65) 5345.35,7723 cw(c5345.35,7748.35) R5.1@5327.42,7730.42 ; R4.1@5377.58,7715.58 ccw(c5359.65,7697.65) 5359.65,7723 ccw(c5359.65,7748.35) R4.1@5377.58,7730.42 ; R95.1@5390,7081 5390,7099 5408,7117 ; R4.1@5392.42,7715.58 cw(c5410.35,7697.65) 5410.35,7723 cw(c5410.35,7748.35) R4.1@5392.42,7730.42 ; R95.1@5400.11,7086.84 cw(c5429.82,7095.18) 5408,7117 ; R3.1@5457.42,7715.58 cw(c5475.35,7697.65) 5475.35,7723 cw(c5475.35,7748.35) R3.1@5457.42,7730.42 ; R2.1@5507.58,7715.58 ccw(c5489.65,7697.65) 5489.65,7723 ccw(c5489.65,7748.35) R2.1@5507.58,7730.42 ; C82.2@5508.39,6411.83 cw(c5494.01,6385.51) 5524,6385.51 ; C83.1@5516.58,6363.42 ccw(c5498.65,6381.35) 5524,6381.35 ccw(c5549.35,6381.35) C83.1@5531.42,6363.42 ; C82.2@5517.5,6430 5524,6423.5 5524,6386 C83.1@5524,6356 5524,6342 5542,6324 5617,6324 5647,6354 5647,7115.94 5645.94,7117 ; R2.1@5522.42,7715.58 cw(c5540.35,7697.65) 5540.35,7723 cw(c5540.35,7748.35) R2.1@5522.42,7730.42 ; 5524,6398.32 cw(c5547.68,6398.32) C82.2@5530.94,6415.06 ; R1.1@5572.58,7715.58 ccw(c5554.65,7697.65) 5554.65,7723 ccw(c5554.65,7748.35) R1.1@5572.58,7730.42 ; R1.1@5587.42,7715.58 cw(c5605.35,7697.65) 5605.35,7723 cw(c5605.35,7748.35) R1.1@5587.42,7730.42 ; R92.2@6030.58,7282.42 ccw(c6019.89,7293.11) 6035,7293.11 ; R92.2@6035,7275 6035,7336 6007,7364 6007,7444 5972,7479 5815.13,7479 5711,7583.13 ; 6035,7307.59 ccw(c6070.59,7307.59) R92.2@6045.42,7282.42 ; 3147,6094 3307,6094 R67.1@3310,6091 C31.1@3375.5,6025.5 ; 5408,7117 5645.94,7117 ; 5645.94,7117 5711,7182.06 5711,7583.13
  other v1: 4939,6249
VDD_5V: C1.1 C2.1 C52.2 C53.1 CE1.1 CE2.1 CE3.1 D2.2 F1.2 HDMI.18 J1.2 J1.4 J4.1 R17.2 R20.2 R58.2 R97.1 R98.1 U2.2 U2.3 | length 12741.3
  Top Layer w10: 2892.25,5586.75 cw(c2924.25,5554.76) R20.2@2924.83,5600 ; 2907.4,5601.9 ccw(c2896.31,5613) R20.2@2912,5613 ; 2909.02,5603.52 cw(c2924.68,5587.86) R20.2@2924.96,5610 ; R20.2@2934.19,5606.81 cw(c2956.38,5584.62) 2956.38,5616 cw(c2956.38,5647.38) R20.2@2934.19,5625.19 ; R17.2@2980.81,5606.81 ccw(c2958.62,5584.62) 2958.62,5616 ccw(c2958.62,5647.38) R17.2@2980.81,5625.19 ; R17.2@2990,5616 R20.2@2925,5616 2921.5,5616 2895.5,5590 2895.5,5493.5 3049.27,5339.73 3655.6,5339.73 J4.1@3679.87,5364 ; v1(3095,6174) 3121,6174 3134,6161 J1.4@3134,6100.54 ; J1.4@3127.24,6143.92 ccw(c3110.9,6160.25) 3134,6160.25 ccw(c3157.1,6160.25) J1.4@3140.76,6143.92 ; v1@5521.73,5547 cw(c5521.73,5513.11) CE3.1@5545.7,5537.07 ; v1@5525.49,5547 ccw(c5525.49,5567.57) CE3.1@5545.86,5564.74 ; CE3.1@5535.96,5566.11 cw(c5514,5569.17) v1(5514,5547) 5532,5547 CE3.1@5570,5585 5649,5585 ; CE3.1@5587.83,5568.39 cw(c5626.01,5532.81) 5626.01,5585 cw(c5626.01,5637.19) CE3.1@5587.83,5601.61 ; CE3.1@5595.15,5561.57 cw(c5649,5511.4) 5649,5585 ; CE3.1@5595.15,5608.43 ccw(c5649,5658.6) 5649,5585 ; HDMI.18@5835,6955.35 5896.35,6955.35 5902.5,6961.5 5949,6961.5 ; v1(5950,7001) 5950.5,7000.5 5950.5,6928.27 5910.17,6887.94 5805.94,6887.94 5772,6854 5772,6446 5898.9,6319.1 5898.9,6094.9 5753,5949 5753,5689 5649,5585
  Top Layer w15: v1(2991,7092) 3097,6986 v1@3097,6305 ; J1.2@3079,6142.16 ccw(c3066.94,6154.22) 3084,6154.22 ccw(c3101.06,6154.22) J1.2@3089,6142.16 ; J1.2@3084,6100.54 3084,6161 v1(3095,6174)
  Bottom Layer w10: 2695,5721 2695,5722.5 ; CE2.1@2740.86,5999.14 ccw(c2704.34,6035.66) 2755.98,6035.66 ; CE1.1@2740.86,6055.86 cw(c2704.34,6019.34) 2755.98,6019.34 ; CE1.1@2740.86,6084.14 ccw(c2704.34,6120.66) 2755.98,6120.66 ; F1.2@2742.82,6153.96 cw(c2711.03,6122.17) 2755.98,6122.17 cw(c2800.94,6122.17) F1.2@2769.15,6153.96 ; CE2.1@2747.93,5992.07 ccw(c2728.48,6011.52) 2755.98,6011.52 ; CE1.1@2747.93,6062.93 cw(c2728.48,6043.48) 2755.98,6043.48 ; CE1.1@2747.93,6077.07 ccw(c2728.48,6096.52) 2755.98,6096.52 ; CE2.1@2752.58,5969.33 cw(c2695.3,5897.08) C1.1@2787.5,5897.08 ; 2755.98,6024.09 cw(c2800.91,6024.09) CE1.1@2769.14,6055.86 ; 2755.98,6030.91 ccw(c2800.91,6030.91) CE2.1@2769.14,5999.14 ; 2755.98,6115.91 ccw(c2800.91,6115.91) CE1.1@2769.14,6084.14 ; F1.2@2755.98,6175 2755.98,6070 2755.98,5989.02 CE2.1@2760,5985 2787.5,5957.5 C1.1@2787.5,5900 2786.5,5899 C2.1@2786.5,5814 ; CE2.1@2758.79,5977.16 cw(c2711.7,5917.76) C1.1@2787.5,5917.76 ; CE2.1@2765,5985 cw(c2728.1,5938.45) 2787.5,5938.45 ; CE2.1@2771.21,5992.84 cw(c2744.5,5959.14) 2787.5,5959.14 ; C2.1@2771.3,5830.7 ccw(c2734.59,5867.41) 2786.5,5867.41 ccw(c2838.41,5867.41) C2.1@2801.7,5830.7 ; C1.1@2772.3,5883.3 cw(c2738.01,5849.01) 2786.5,5849.01 ; C1.1@2772.3,5916.7 ccw(c2735.59,5953.41) 2787.5,5953.41 ccw(c2839.41,5953.41) C1.1@2802.7,5916.7 ; C2.1@2778.37,5823.63 ccw(c2758.74,5843.26) 2786.5,5843.26 ccw(c2814.26,5843.26) C2.1@2794.63,5823.63 ; C1.1@2779.37,5909.63 ccw(c2759.74,5929.26) 2787.5,5929.26 ccw(c2815.26,5929.26) C1.1@2795.63,5909.63 ; 2786.5,5844.18 cw(c2841.82,5844.18) C1.1@2802.7,5883.3 ; 2786.5,5868.32 cw(c2817.68,5868.32) C1.1@2795.63,5890.37 ; v1(3095,6174) 3096,6175 v1@3095,6175 ; D2.2@3184.17,7802.21 ccw(c3171.09,7828) 3200,7828 ; D2.2@3188.69,7793.3 ccw(c3179.35,7811.71) 3200,7811.71 ccw(c3220.65,7811.71) D2.2@3211.31,7793.3 ; D2.2@3200,7735 D2.2@3200,7761 3200,7828 ; D2.2@3215.83,7802.21 cw(c3228.91,7828) 3200,7828 ; R58.2@5198,5651 ccw(c5224.56,5651) 5205.78,5632.22 ; R58.2@5205,5654 5205,5633 5292,5546 5387,5546 ; R58.2@5208,5651 ccw(c5258.7,5651) 5222.85,5615.15 ; R58.2@5218,5651 ccw(c5292.84,5651) 5239.92,5598.08 ; U2.3@5388.82,5600 5388.82,5547.82 5387,5546 ; U2.2@5414.41,5600 5414.41,5549.59 5418,5546 ; v1(5514,5547) 5513,5546 5418,5546 ; v1@5949.5,7001.5 5963,7015 C53.1@5979,7015 C52.2@5979,7080 5979,7083 R98.1@6041,7145 R97.1@6041,7210 ; v1@5954.94,7006.94 cw(c5969.42,6992.46) C53.1@5975.16,7012.12 ; C53.1@5969.81,7024.19 ccw(c5947.62,7046.38) 5979,7046.38 ccw(c6010.38,7046.38) C53.1@5988.19,7024.19 ; C52.2@5969.81,7070.81 cw(c5947.62,7048.62) 5979,7048.62 cw(c6010.38,7048.62) C52.2@5988.19,7070.81 ; C52.2@5982,7093 ccw(c5982,7109.9) 5993.95,7097.95 ; C52.2@5995,7080 cw(c6040.87,7080) 6008.44,7112.44 ; 6013.69,7117.69 ccw(c5986.37,7145) R98.1@6025,7145 ; 6020.93,7124.93 cw(c6038,7107.86) R98.1@6038,7132 ; R98.1@6031.81,7154.19 ccw(c6009.62,7176.38) 6041,7176.38 ccw(c6072.38,7176.38) R98.1@6050.19,7154.19 ; R97.1@6031.81,7200.81 cw(c6009.62,7178.62) 6041,7178.62 cw(c6072.38,7178.62) R97.1@6050.19,7200.81 ; R97.1@6043.18,7212.88 6082,7251.71 6082,7327 6032,7377 6032,7455 5985,7502 5831,7502 5730,7603 5730,7674.87 5615.12,7789.75 3482.25,7789.75 3417.5,7854.5 3226.5,7854.5 3200,7828 ; R97.1@6044,7223 ccw(c6044,7245.43) 6059.86,7229.57 ; R97.1@6057,7210 cw(c6097.34,7210) 6068.81,7238.52 ; 5387,5546 5418,5546
  Bottom Layer w15: 2695,5721 2695,5539 2743,5491 v1(2896,5491) ; 2695,5722.5 C2.1@2786.5,5814 ; 2751.5,5779 cw(c2786.5,5744.01) C2.1@2786.5,5793.5 ; 2755.13,5782.63 ccw(c2725.25,5812.5) C2.1@2767.5,5812.5 ; CE1.1@2755.98,6070 CE1.1@2760,6070 ; F1.2@2755.98,6175 v1@3095,6175 ; F1.2@2767.38,6163.6 cw(c2794.91,6136.08) 2794.91,6175 cw(c2794.91,6213.92) F1.2@2767.38,6186.4 ; v1(2991,7092) 2962,7121 2962,7497 D2.2@3200,7735 ; v1(3095,6174) v1@3095,6175 ; v1@3095,6305 v1@3095,6175 ; 3133.21,7668.21 ccw(c3050.41,7751) D2.2@3167.5,7751 ; 3158.81,7693.81 ccw(c3101.62,7751) D2.2@3182.5,7751 ; 3171.83,7706.83 cw(c3200,7678.67) D2.2@3200,7718.5
  other v1: 3096,6305
VDD_ADC: J1.86 J4.41 | length 926.3
  Top Layer w6.5: J1.86@5176,6055.93 cw(c5156.68,6036.61) 5184,6036.61 cw(c5211.32,6036.61) J1.86@5192,6055.93 ; J1.86@5184,6100.54 5184,6035 5209,6010 5209,5857 5214.25,5851.75 5214.25,5404.42 J4.41@5254.67,5364 ; 5216.71,5401.96 ccw(c5246.27,5431.51) J4.41@5251.83,5390.09 ; 5221.69,5396.98 cw(c5193.64,5368.92) J4.41@5233.31,5368.92 ; 5226,5392.67 ccw(c5248.47,5415.13) J4.41@5252.69,5383.65 ; 5232.79,5385.88 cw(c5215.83,5368.92) J4.41@5239.81,5368.92
VDD_ETH: J1.8 J1.10 R50.1 | length 1090.7
  Top Layer w15: v2@3176,6773 3182.33,6766.67 3182.33,6357.67 v2(3234,6306) ; J1.8@3229,6142.16 ccw(c3216.94,6154.22) 3234,6154.22 ccw(c3251.06,6154.22) J1.8@3239,6142.16 ; J1.8@3234,6100.54 v1@3234,6178 ; v1(3235,6178) 3272,6178 3284,6166 J1.10@3284,6100.54 ; J1.10@3279,6142.16 ccw(c3266.94,6154.22) 3284,6154.22 ccw(c3301.06,6154.22) J1.10@3289,6142.16
  Bottom Layer w15: R50.1@3022.58,6742.42 ccw(c3004.65,6760.35) 3030,6760.35 ccw(c3055.35,6760.35) R50.1@3037.42,6742.42 ; R50.1@3030,6735 3030,6769 v2(3031,6770) v2@3179,6770 ; v1@3234,6180 v2(3234,6306)
  other v2: 3179,6772
VDD_IN: 5V/2A.1 F1.1 | length 794.8
  Bottom Layer w10: 5V/2A.1@2578.72,5993.54 ccw(c2518.97,6053.29) 2603.47,6053.29 ccw(c2687.97,6053.29) 5V/2A.1@2628.22,5993.54 ; 5V/2A.1@2585.79,5986.47 ccw(c2543.11,6029.15) 2603.47,6029.15 ccw(c2663.83,6029.15) 5V/2A.1@2621.15,5986.47 ; 5V/2A.1@2603.47,5930.79 2603.47,6148.47 F1.1@2630,6175 ; 2603.47,6058.12 cw(c2739.01,6058.12) F1.1@2643.17,6153.96 ; 2603.47,6082.26 cw(c2714.86,6082.26) F1.1@2636.1,6161.03 ; 2603.47,6106.4 cw(c2690.72,6106.4) F1.1@2629.03,6168.1 ; 2603.47,6130.55 cw(c2666.58,6130.55) F1.1@2621.95,6175.17
XDMA_EVENT_INTR0: J1.85 J4.15 U9.1 | length 2047
  Top Layer w6.5: J4.15@4231.05,5364 4272,5404.95 ; J4.15@4231.64,5377.26 ccw(c4233.47,5403.18) 4251.85,5384.8 ; J4.15@4232.1,5383.74 ccw(c4234.81,5421.99) 4261.92,5394.88 ; J4.15@4232.56,5390.22 ccw(c4236.14,5440.81) 4272,5404.95 ; J4.15@4245.9,5368.92 cw(c4269.89,5368.92) 4252.93,5385.88 ; J4.15@4252.4,5368.92 cw(c4292.08,5368.92) 4264.03,5396.98 ; v1(4480,5598) 4480,5520 4445,5485 4279,5485 4272,5478 4272,5404.95 ; v1@5159.68,6271 5159.68,6032.47 5184,6008.15 ; J1.85@5176,5902.38 cw(c5156.68,5883.06) 5184,5883.06 cw(c5211.32,5883.06) J1.85@5192,5902.38 ; J1.85@5176.65,5992.22 ccw(c5163.06,6008.15) 5184,6008.15 ; v1(5183,5785) 5184,5786 J1.85@5184,5947 5184,6008.15 ; J1.85@5191.35,5992.22 cw(c5204.94,6008.15) 5184,6008.15
  Bottom Layer w6.5: v1@4480,5597 5006,5597 5183,5774 v1(5183,5785) ; v1@5161.75,6271 5161.75,6330.8 U9.1@5178.62,6347.67 ; U9.1@5174,6347.67 cw(c5162.83,6347.67) 5170.73,6339.78 cw(c5178.62,6331.88) U9.1@5178.62,6343.05
  other v1: 5160,6274
XDMA_EVENT_INTR1: J1.87 J4.16 | length 1485.2
  Top Layer w6.5: J4.16@4219.4,5465.56 ccw(c4205.41,5487.05) 4231.05,5487.05 ; J4.16@4222.94,5460.11 ccw(c4213.21,5475.06) 4231.05,5475.06 ccw(c4248.88,5475.06) J4.16@4239.15,5460.11 ; J4.16@4231.05,5442.74 4231.05,5487.05 ; J4.16@4242.7,5465.56 cw(c4256.69,5487.05) 4231.05,5487.05 ; v1@4446.58,5574.42 4446.58,5532.58 4412,5498 4242,5498 4231.05,5487.05 ; J1.87@5226,5902.38 cw(c5206.68,5883.06) 5234,5883.06 cw(c5261.32,5883.06) J1.87@5242,5902.38 ; J1.87@5234,5947 5234,5861 v1@5236,5859
  Bottom Layer w6.5: v1@4441.75,5576.25 5013.25,5576.25 5236,5799 v1@5236,5859
  other v1: 4447,5578 5236,5868
YE_N: ETHERNET.11 J1.13 | length 2248
  Top Layer w6.5: ETHERNET.11@2292.09,6483.17 2336,6439.26 ; ETHERNET.11@2292.48,6469.43 cw(c2293.33,6439.27) 2314.66,6460.6 cw(c2335.99,6481.93) ETHERNET.11@2305.83,6482.78 ; ETHERNET.11@2292.66,6462.93 cw(c2293.91,6418.51) 2325.33,6449.93 cw(c2356.75,6481.35) ETHERNET.11@2312.33,6482.6 ; ETHERNET.11@2292.84,6456.43 cw(c2294.49,6397.76) 2336,6439.26 ; ETHERNET.11@2318.83,6482.42 ccw(c2377.5,6480.77) 2336,6439.26 ; J1.13@3376,5902.38 cw(c3356.68,5883.06) 3384,5883.06 cw(c3411.32,5883.06) J1.13@3392,5902.38 ; J1.13@3384,5947 3384,5868.75 3355.25,5840 3169.93,5840 3167.87,5837.94 3064.62,5734.69 2618.31,5734.69 2543,5810 2296,5810 2263,5843 2263,6284 2336,6357 2336,6439.26
YE_P: ETHERNET.12 J1.15 | length 2132.2
  Top Layer w6.5: 2260.04,6331.04 ccw(c2233.89,6357.19) ETHERNET.12@2267.66,6372.27 ; 2266.72,6337.72 ccw(c2243.13,6361.32) ETHERNET.12@2273.6,6374.92 ; 2273.4,6344.4 ccw(c2252.37,6365.44) ETHERNET.12@2279.53,6377.57 ; 2280.08,6351.08 ccw(c2261.61,6369.56) ETHERNET.12@2285.47,6380.21 ; 2280.7,6351.7 cw(c2292.09,6340.32) ETHERNET.12@2292.09,6356.42 ; ETHERNET.12@2292.09,6383.17 2292.09,6363.09 2250,6321 2250,5830 2283,5797 2536,5797 2611.31,5721.69 3070,5721.69 3173.25,5824.94 3373.94,5824.94 3434,5885 ; J1.15@3426.44,5901.97 cw(c3411.19,5885) 3434,5885 ; J1.15@3434,5947 3434,5885 ; J1.15@3441.56,5901.97 ccw(c3456.81,5885) 3434,5885
pads on no net: 5V/2A.2 "TF CARD.14" "TF CARD.15" BOOT.0 BOOT.3 DEBUG.0 DEBUG.4 DEBUG.8 DEBUG.9 ETHERNET.13 ETHERNET.14 ETHERNET.15 ETHERNET.16 H4.1 H5.1 H6.1 H7.1 HDMI.14 J1.101 J1.102 J1.103 J1.104 J2.101 J2.102 J2.103 J2.104 J3.0 J3.0/2 JTAG.6 M1.1 M2.1 M3.1 M4.1 OTG.0 OTG.8 OTG.9 POWER.0 RESET.0 U3.1 U3.2 U3.10 U3.11 U3.12 U3.13 U3.14 U3.15 U3.16 U3.17 U3.18 U3.19 U3.20 U3.21 U3.22 U3.23 U3.24 U3.27 U3.28 U6.26 U6.28
copper on no net:
  other v2: 5755,7307

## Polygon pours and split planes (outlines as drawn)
DGND on Bottom Layer "Top Layer-DGND" (solid, remove dead copper, pour order 17): 2134,8032 2137,8035 6182,8035 6182,5312 6180,5310 6179,5309 2127,5309 2127,8034 2126,8035 2129,8032 2134,8032
DGND on Top Layer "Bottom Layer-DGND" (solid, remove dead copper, pour order 16): 2134,8032 2137,8035 6182,8035 6182,5312 6180,5310 6179,5309 2127,5309 2127,8034 2126,8035 2129,8032 2134,8032

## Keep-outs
Keep-Out Layer:
  the board outline again, w7.87

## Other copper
Top Layer:
  rectangle net DGND: 5532,7294 5548,7347.63
  rectangle net GND_EARTH: 5821,6798 6155,6856
  rectangle net GND_EARTH: 5823,7368 6156,7429
  rectangle net DGND: 5042,7723 5078,7768
  rectangle net DGND: 4977,7724 5013,7769
  rectangle net DGND: 4912,7723 4948,7768
  rectangle net DGND: 4847,7724 4883,7769
  rectangle net DGND: 5107,7724 5143,7769
  rectangle net VCC3V3_BAT: 3070,5888.39 3141,5896
  rectangle net DGND: 5109.3,6567.7 5162.7,6579.4
  pour cut-out: 2135,6963 2912.85,6963 2914.92,6960.93 2914.92,6327.07 2134,6327.07 2137,6330.07 2137,6960.93
  pour cut-out: 5117,6611 5163,6611 5162.7,6579.4 5162.09,6580 5117,6580
  pour cut-out: 4313.57,5993.46 4355.54,5993.46 4357,5992 4354.43,5989.43 4354.43,5892 4313.57,5892
  pour cut-out: 4314,5997 4348,5997 4348,5893 4347,5892 4319,5892 4319,6000 4316,6003
  pour cut-out: 4162,7457 4240,7457 4240,7348 4162,7348
  pour cut-out: 5138,6955 5188,6955 5188,6910 5138,6910
  pour cut-out: 5315,6956 5346,6956 5346,6908 5315,6908
  pour cut-out: 5083,6782 5116,6782 5116,6752 5083,6752
  pour cut-out: 5131.73,6909.84 5182.39,6909.84 5182.39,6613.39 5181,6612 5132,6612 5132,6909.57
  pour cut-out: 5182.39,6906.89 5410.89,6906.89 5410.9,6906.9 5410.9,6855.61 5182.39,6855.61
  pour cut-out: 5367,6856 5411,6856 5410.9,6627.72 5410.24,6627.07 5366,6627
  pour cut-out: 5182,6682 5367,6682 5369,6680 5369,6627 5182,6627
  pour cut-out: 5086,6625 5132,6625 5132,6579 5086,6579
  pour cut-out: 5513.57,6166.73 5542.73,6166.73 5543,6167 5556,6167 5556,5884 5514.9,5884 5513.57,5882.67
